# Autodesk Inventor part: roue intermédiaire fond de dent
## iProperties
Shininess: 64.0
Length Units: 11269
Angle Units: 11279
Time Units: 11290
Mass Units: 11283
Length Display Precision: 3
Angle Display Precision: 2
Compacted: True
Part Number: roue intermédiaire fond de dent
Document SubType Name: Modeling
Created: 2004-09
Material: Par défaut
Designer: Administrateur
Density: 1 g/cm^3
Density: 0.0
Volumn: 0.0
Area: 0.0
PropertySet Name: Model Information
Control State: 0
Master: False
Checked Out: False
Author: Administrateur
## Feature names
1. Extrusion1
2. Extrusion2
3. Extrusion3
4. Extrusion4
5. Extrusion5
6. Chanfrein1 [Chamfer]
